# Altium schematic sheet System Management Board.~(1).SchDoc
size 594 x 420 mm
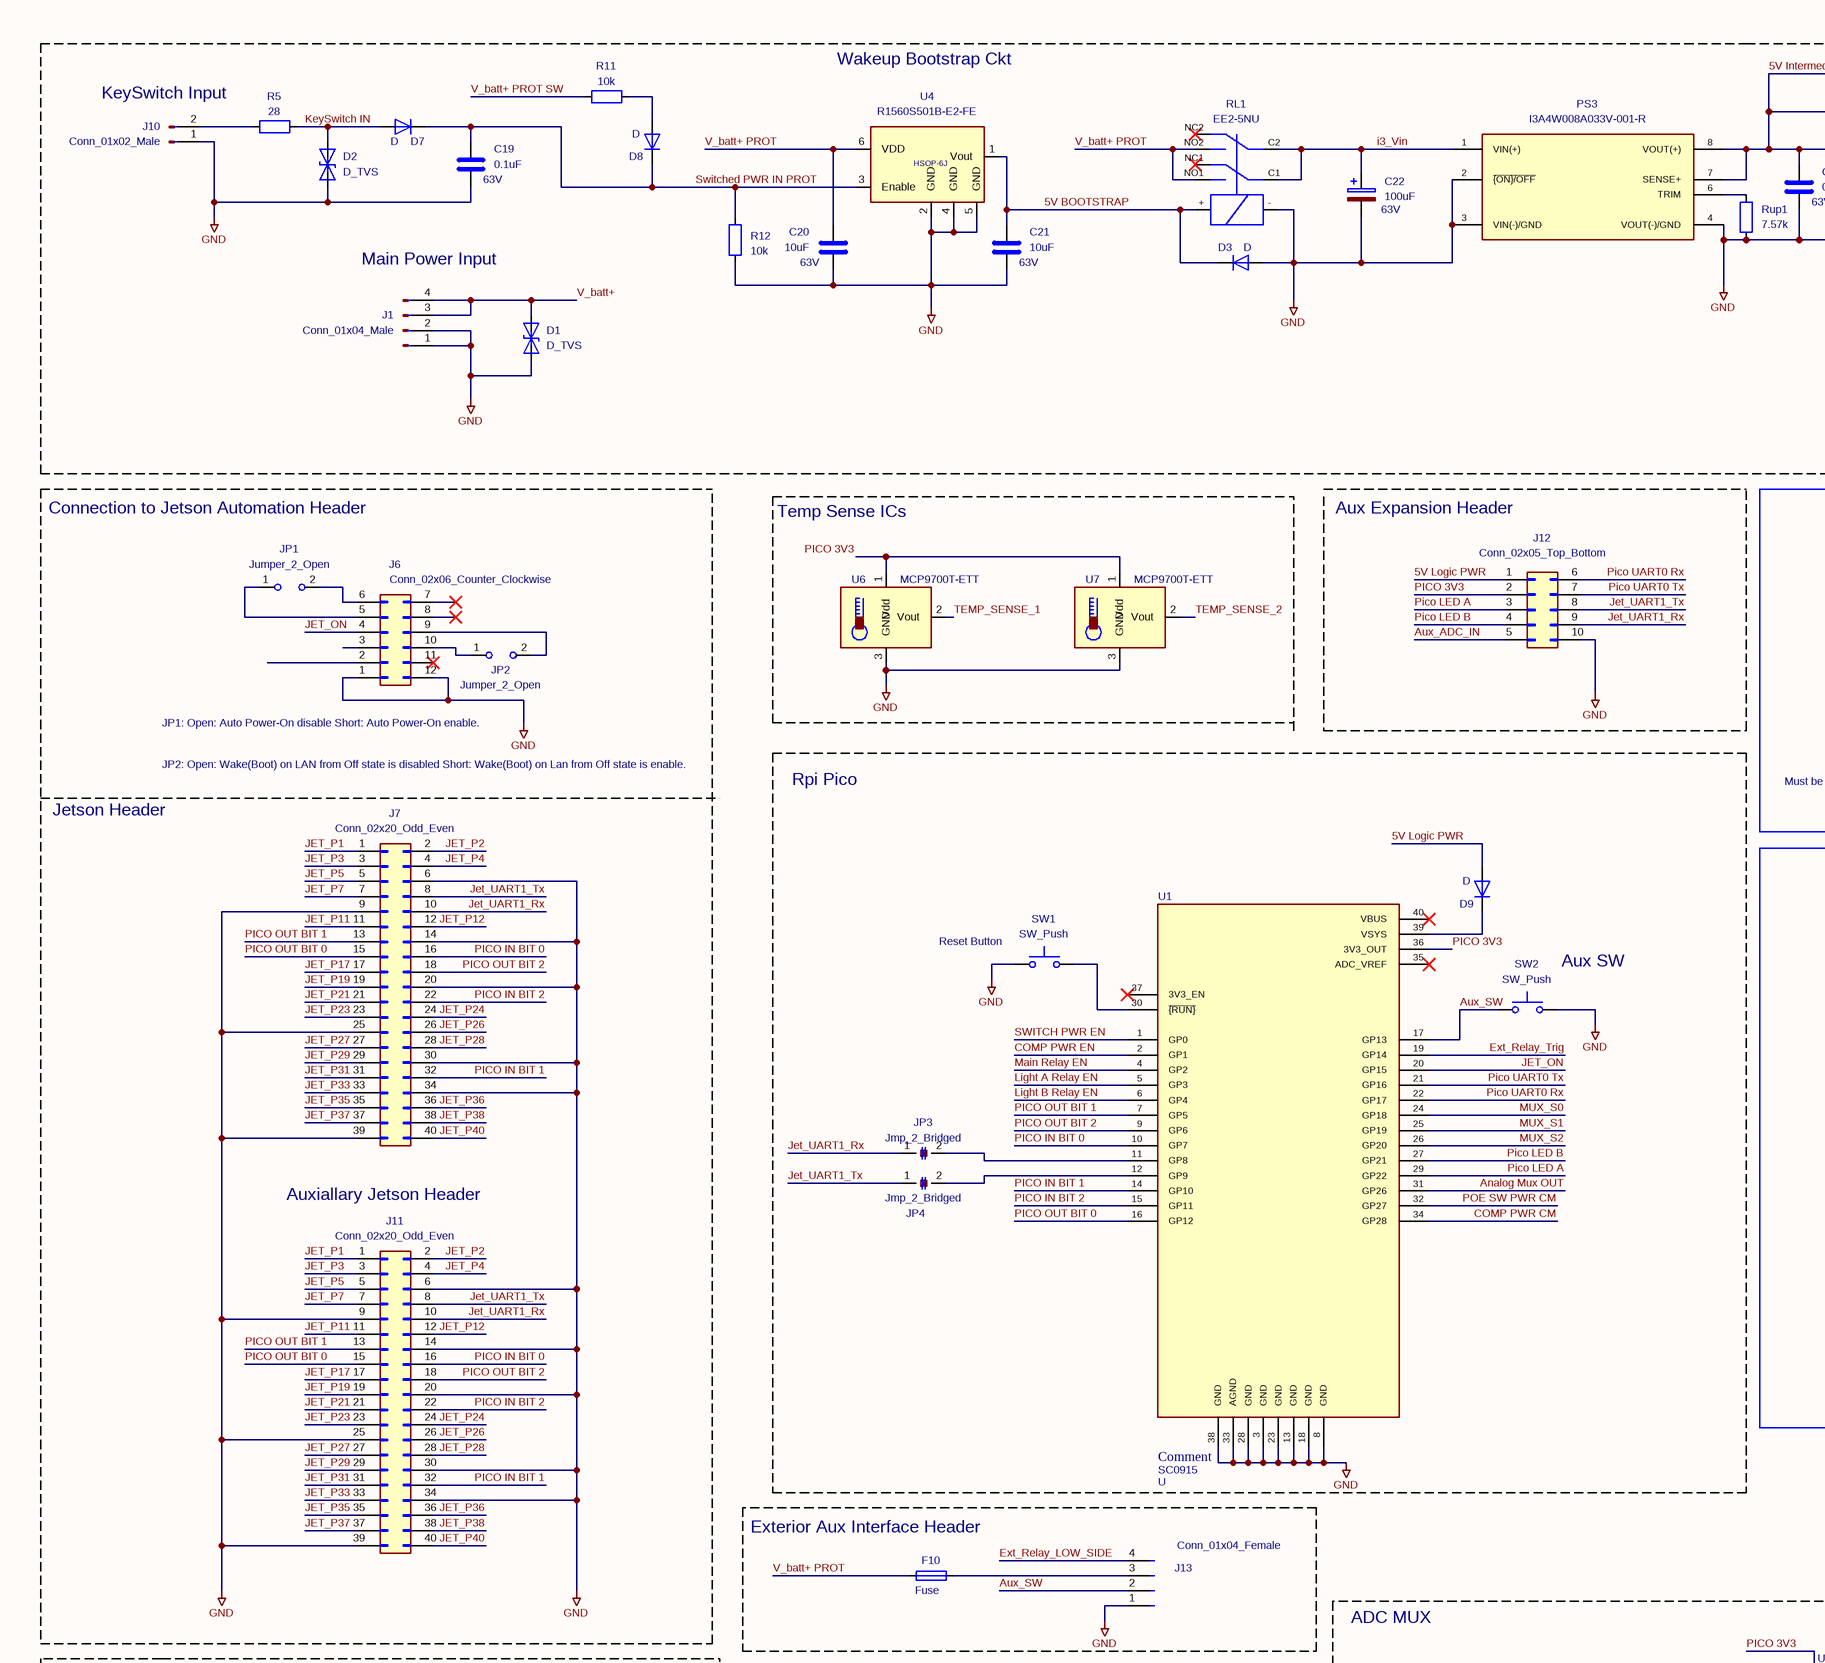
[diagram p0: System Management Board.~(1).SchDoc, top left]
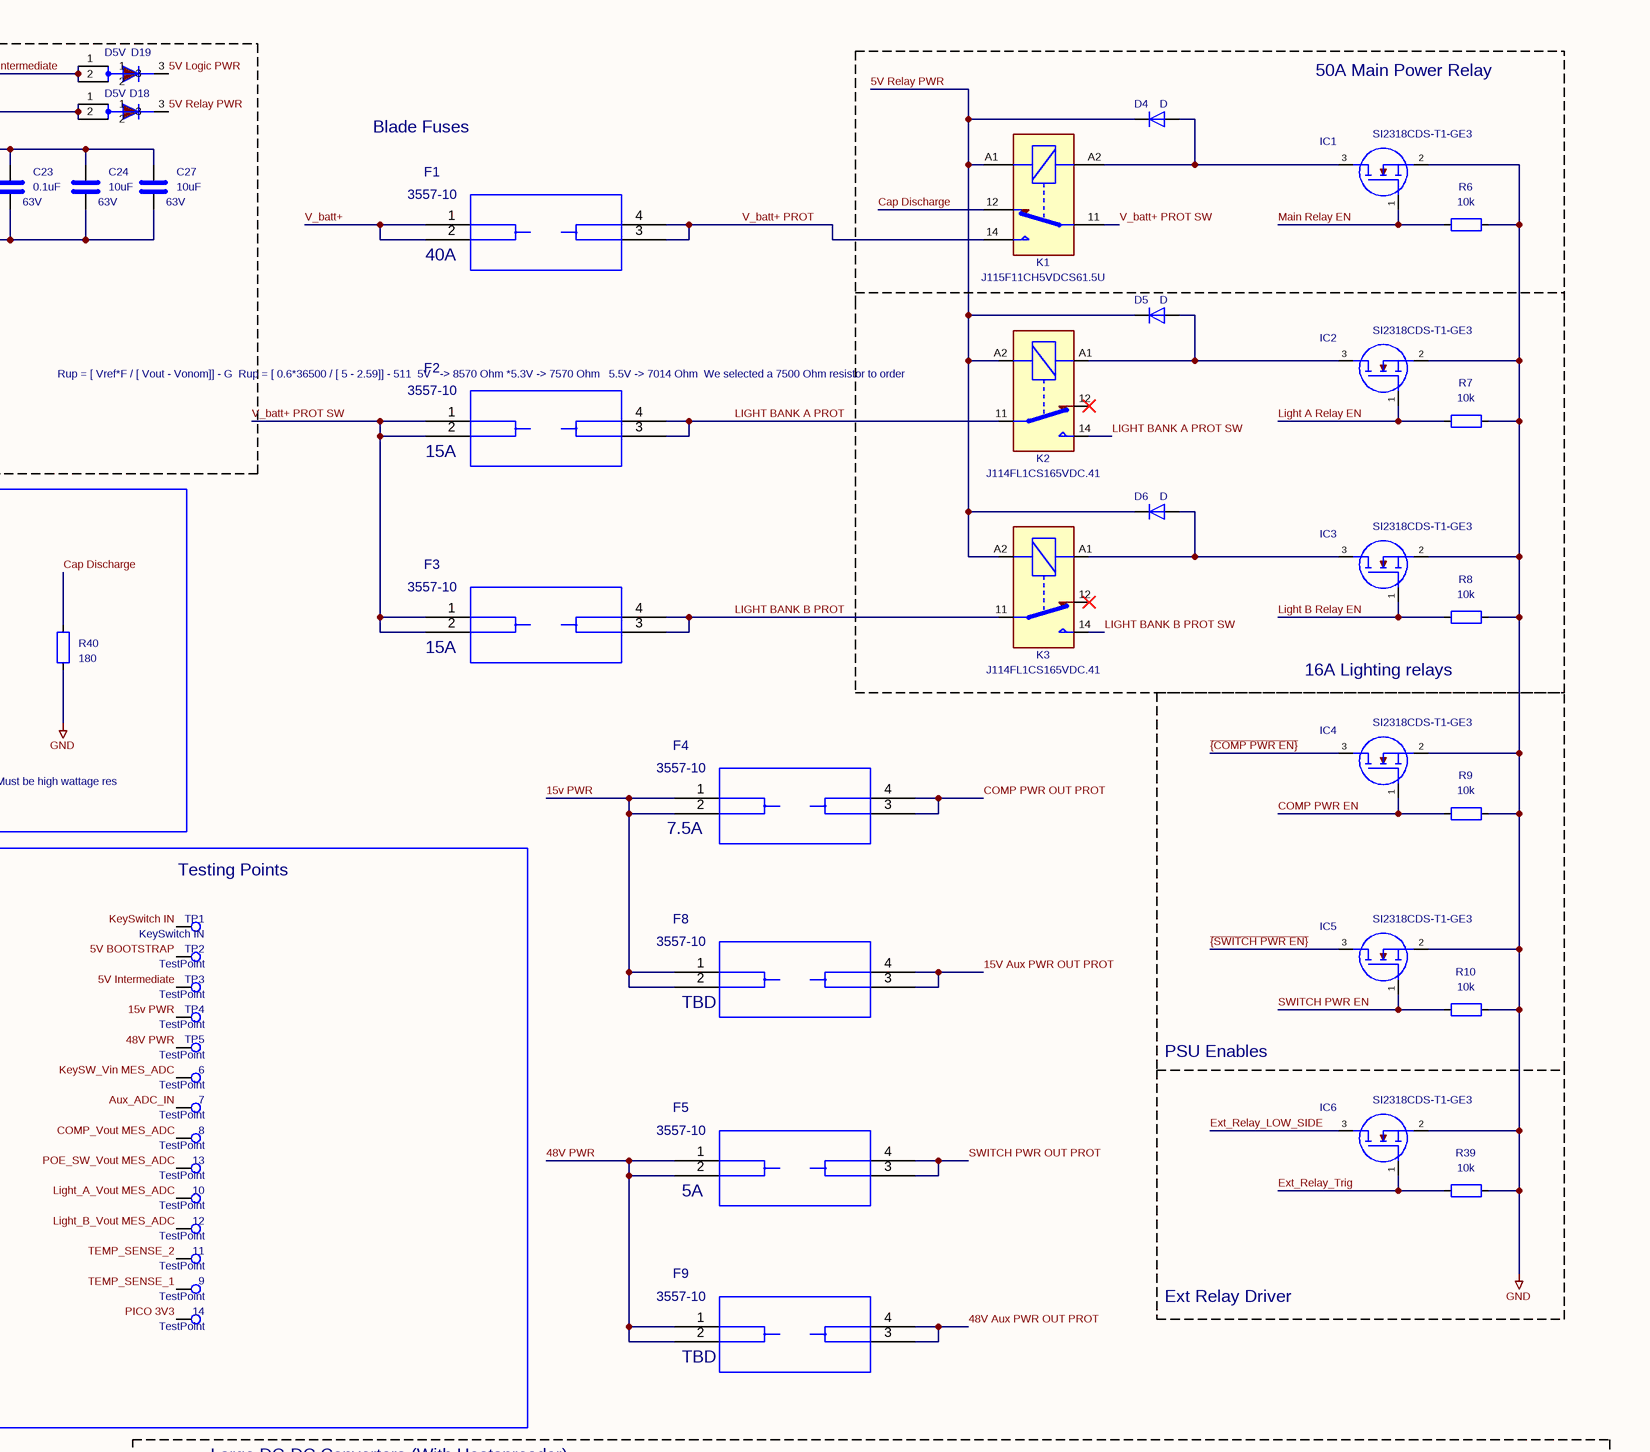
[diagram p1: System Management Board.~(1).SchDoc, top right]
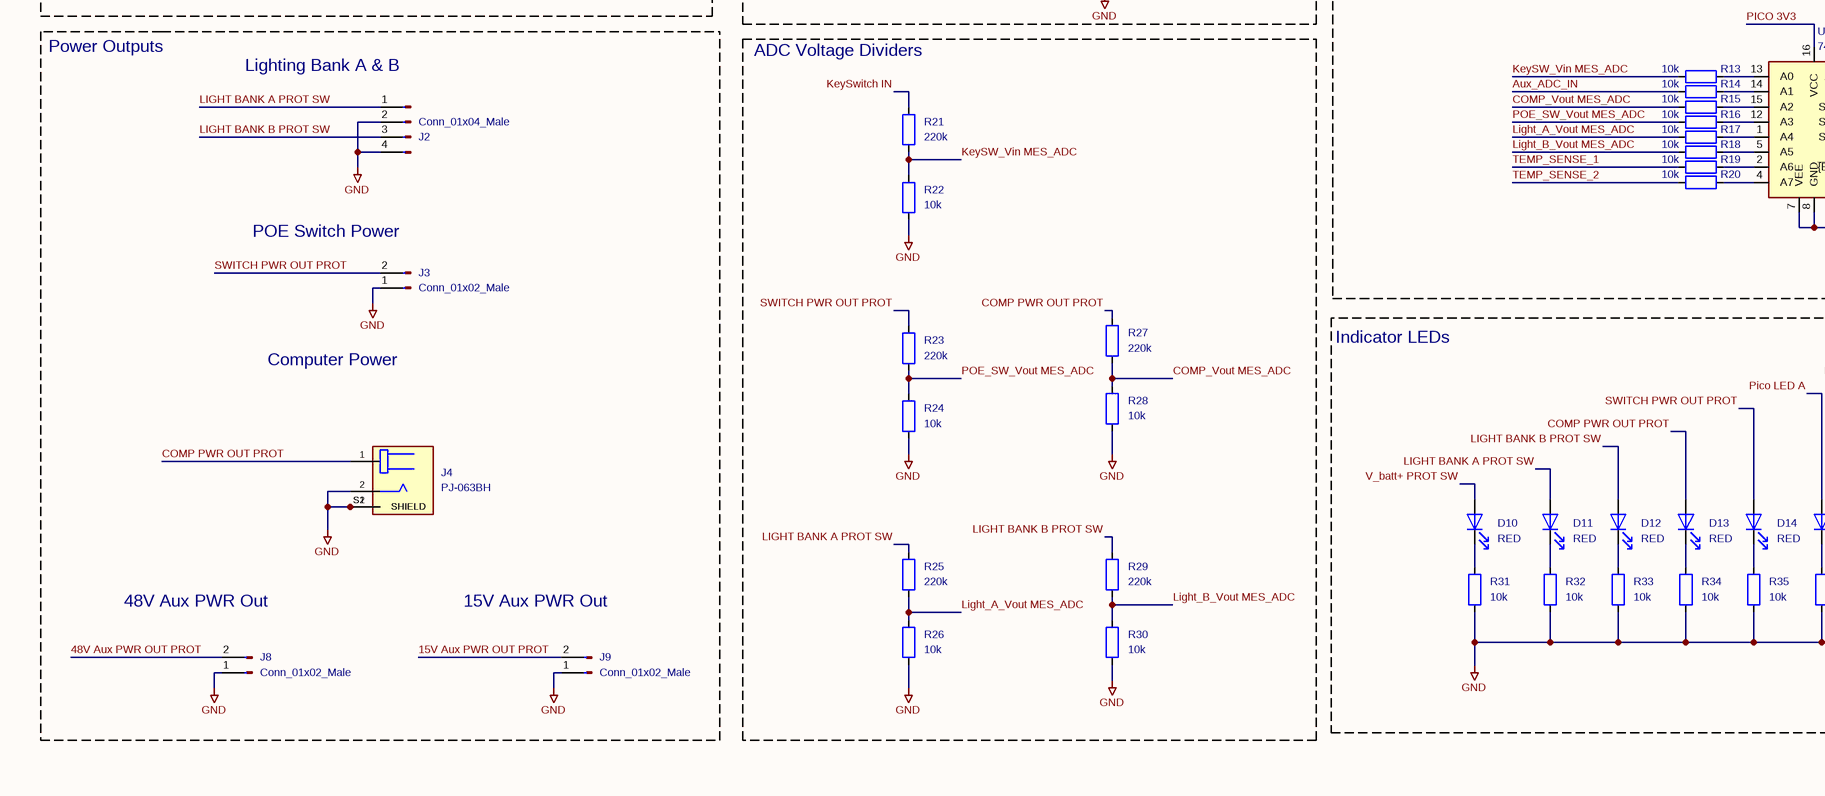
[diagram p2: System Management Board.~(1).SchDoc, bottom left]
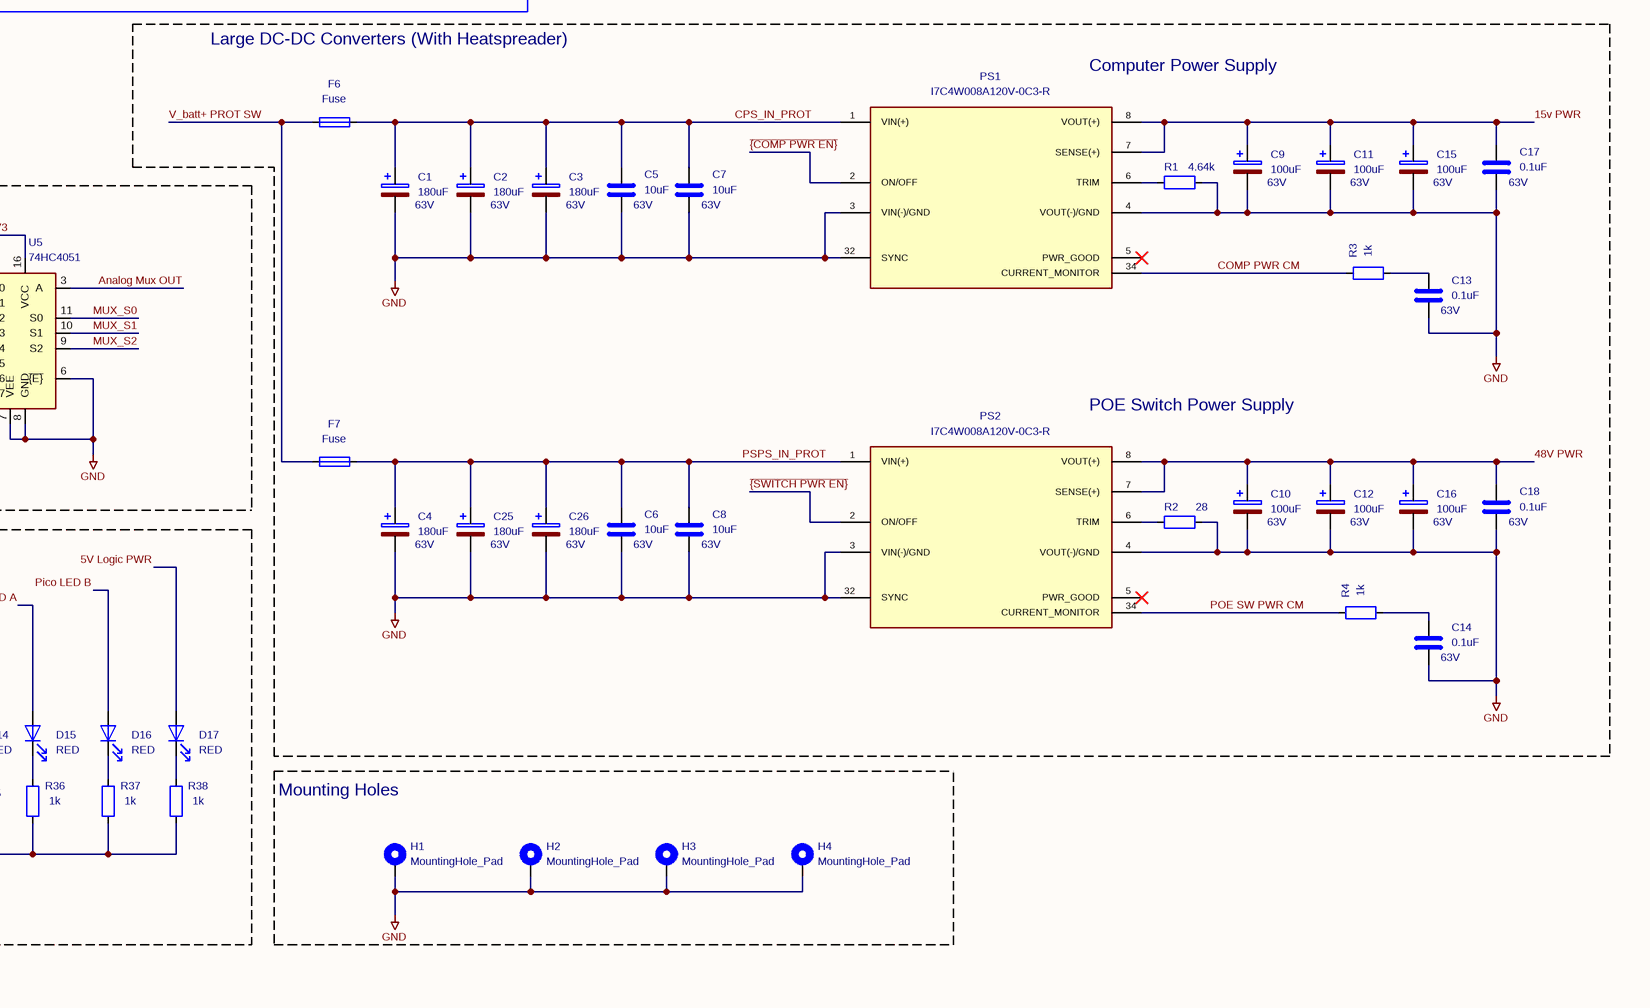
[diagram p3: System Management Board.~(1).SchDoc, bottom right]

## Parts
6  value TestPoint  [TestPoint_Pad_D1.0mm]  (hidden comment: Comment)
7  value TestPoint  [TestPoint_Pad_D1.0mm]  (hidden comment: Comment)
8  value TestPoint  [TestPoint_Pad_D1.0mm]  (hidden comment: Comment)
9  value TestPoint  [TestPoint_Pad_D1.0mm]  (hidden comment: Comment)
10  value TestPoint  [TestPoint_Pad_D1.0mm]  (hidden comment: Comment)
11  value TestPoint  [TestPoint_Pad_D1.0mm]  (hidden comment: Comment)
12  value TestPoint  [TestPoint_Pad_D1.0mm]  (hidden comment: Comment)
13  value TestPoint  [TestPoint_Pad_D1.0mm]  (hidden comment: Comment)
14  value TestPoint  [TestPoint_Pad_D1.0mm]  (hidden comment: Comment)
C1  value 180uF  Voltage: 63V  [CP_Elec_10x12.6]  (hidden comment: Comment)
C2  value 180uF  Voltage: 63V  [CP_Elec_10x12.6]  (hidden comment: Comment)
C3  value 180uF  Voltage: 63V  [CP_Elec_10x12.6]  (hidden comment: Comment)
C4  value 180uF  Voltage: 63V  [CP_Elec_10x12.6]  (hidden comment: Comment)
C5  value 10uF  Voltage: 63V  [C_1210_3225Metric]  (hidden comment: Comment)
C6  value 10uF  Voltage: 63V  [C_1210_3225Metric]  (hidden comment: Comment)
C7  value 10uF  Voltage: 63V  [C_1210_3225Metric]  (hidden comment: Comment)
C8  value 10uF  Voltage: 63V  [C_1210_3225Metric]  (hidden comment: Comment)
C9  value 100uF  Voltage: 63V  [CP_Elec_10x12.6]  (hidden comment: Comment)
C10  value 100uF  Voltage: 63V  [CP_Elec_10x12.6]  (hidden comment: Comment)
C11  value 100uF  Voltage: 63V  [CP_Elec_10x12.6]  (hidden comment: Comment)
C12  value 100uF  Voltage: 63V  [CP_Elec_10x12.6]  (hidden comment: Comment)
C13  value 0.1uF  Voltage: 63V  [C_1206_3216Metric]  (hidden comment: Comment)
C14  value 0.1uF  Voltage: 63V  [C_1206_3216Metric]  (hidden comment: Comment)
C15  value 100uF  Voltage: 63V  [CP_Elec_10x12.6]  (hidden comment: Comment)
C16  value 100uF  Voltage: 63V  [CP_Elec_10x12.6]  (hidden comment: Comment)
C17  value 0.1uF  Voltage: 63V  [C_1210_3225Metric]  (hidden comment: Comment)
C18  value 0.1uF  Voltage: 63V  [C_1210_3225Metric]  (hidden comment: Comment)
C19  value 0.1uF  Voltage: 63V  [C_1206_3216Metric]  (hidden comment: Comment)
C20  value 10uF  Voltage: 63V  [C_1210_3225Metric]  (hidden comment: Comment)
C21  value 10uF  Voltage: 63V  [C_1210_3225Metric]  (hidden comment: Comment)
C22  value 100uF  Voltage: 63V  [CP_Elec_10x12.6]  (hidden comment: Comment)
C23  value 0.1uF  Voltage: 63V  [C_1206_3216Metric]  (hidden comment: Comment)
C24  value 10uF  Voltage: 63V  [C_1210_3225Metric]  (hidden comment: Comment)
C25  value 180uF  Voltage: 63V  [CP_Elec_10x12.6]  (hidden comment: Comment)
C26  value 180uF  Voltage: 63V  [CP_Elec_10x12.6]  (hidden comment: Comment)
C27  value 10uF  Voltage: 63V  [C_1210_3225Metric]  (hidden comment: Comment)
D1  value D_TVS  [D_SMA]  (hidden comment: Comment)
D2  value D_TVS  [D_SMA]  (hidden comment: Comment)
D3  value D  [D_SOD-123F]  (hidden comment: Comment)
D4  value D  [D_SOD-123F]  (hidden comment: Comment)
D5  value D  [D_SOD-123F]  (hidden comment: Comment)
D6  value D  [D_SOD-123F]  (hidden comment: Comment)
D7  value D  [D_SOD-123F]  (hidden comment: Comment)
D8  value D  [D_SOD-123F]  (hidden comment: Comment)
D9  value D  [D_SOD-123F]  (hidden comment: Comment)
D10  value RED  [LED_1206_3216Metric]  (hidden comment: Comment)
D11  value RED  [LED_1206_3216Metric]  (hidden comment: Comment)
D12  value RED  [LED_1206_3216Metric]  (hidden comment: Comment)
D13  value RED  [LED_1206_3216Metric]  (hidden comment: Comment)
D14  value RED  [LED_1206_3216Metric]  (hidden comment: Comment)
D15  value RED  [LED_1206_3216Metric]  (hidden comment: Comment)
D16  value RED  [LED_1206_3216Metric]  (hidden comment: Comment)
D17  value RED  [LED_1206_3216Metric]  (hidden comment: Comment)
D18  value D5V  [POWERDI5_DIO]  (hidden comment: Comment)
D19  value D5V  [POWERDI5_DIO]  (hidden comment: Comment)
F1  value 3557-10  [3557-10]  (hidden comment: Comment)
F2  value 3557-10  [3557-10]  (hidden comment: Comment)
F3  value 3557-10  [3557-10]  (hidden comment: Comment)
F4  value 3557-10  [3557-10]  (hidden comment: Comment)
F5  value 3557-10  [3557-10]  (hidden comment: Comment)
F6  value Fuse  [FUSC9830X318N]  (hidden comment: Comment)
F7  value Fuse  [FUSC9830X318N]  (hidden comment: Comment)
F8  value 3557-10  [3557-10]  (hidden comment: Comment)
F9  value 3557-10  [3557-10]  (hidden comment: Comment)
F10  value Fuse  [Fuse_1206_3216Metric_Pad1.42x1.75mm_HandSolder]  (hidden comment: Comment)
H1  value MountingHole_Pad  [MountingHole_3.2mm_M3_DIN965_Pad]  (hidden comment: Comment)
H2  value MountingHole_Pad  [MountingHole_3.2mm_M3_DIN965_Pad]  (hidden comment: Comment)
H3  value MountingHole_Pad  [MountingHole_3.2mm_M3_DIN965_Pad]  (hidden comment: Comment)
H4  value MountingHole_Pad  [MountingHole_3.2mm_M3_DIN965_Pad]  (hidden comment: Comment)
IC1  value SI2318CDS-T1-GE3  [SOT95P237X112-3N]  (hidden comment: Comment)
IC2  value SI2318CDS-T1-GE3  [SOT95P237X112-3N]  (hidden comment: Comment)
IC3  value SI2318CDS-T1-GE3  [SOT95P237X112-3N]  (hidden comment: Comment)
IC4  value SI2318CDS-T1-GE3  [SOT95P237X112-3N]  (hidden comment: Comment)
IC5  value SI2318CDS-T1-GE3  [SOT95P237X112-3N]  (hidden comment: Comment)
IC6  value SI2318CDS-T1-GE3  [SOT95P237X112-3N]  (hidden comment: Comment)
J1  value Conn_01x04_Male  [1924321]  (hidden comment: Comment)
J2  value Conn_01x04_Male  [1924321]  (hidden comment: Comment)
J3  value Conn_01x02_Male  [1843606]  (hidden comment: Comment)
J4  value PJ-063BH  [CUI_PJ-063BH]  (hidden comment: Comment)
J6  value Conn_02x06_Counter_Clockwise  [PinHeader_2x06_P2.54mm_Vertical]  (hidden comment: Comment)
J7  value Conn_02x20_Odd_Even  [PinHeader_2x20_P2.54mm_Horizontal]  (hidden comment: Comment)
J8  value Conn_01x02_Male  [1843606]  (hidden comment: Comment)
J9  value Conn_01x02_Male  [1843606]  (hidden comment: Comment)
J10  value Conn_01x02_Male  [1843606]  (hidden comment: Comment)
J11  value Conn_02x20_Odd_Even  [PinHeader_2x20_P2.54mm_Vertical]  (hidden comment: Comment)
J12  value Conn_02x05_Top_Bottom  [PinSocket_2x05_P2.54mm_Vertical]  (hidden comment: Comment)
J13  value Conn_01x04_Female  [PinHeader_1x04_P2.54mm_Vertical]  (hidden comment: Comment)
JP1  value Jumper_2_Open  [PinHeader_1x02_P2.54mm_Vertical]  (hidden comment: Comment)
JP2  value Jumper_2_Open  [PinHeader_1x02_P2.54mm_Vertical]  (hidden comment: Comment)
JP3  value Jmp_2_Bridged  [SolderJumper-2_P1.3mm_Bridged_Pad1.0x1.5mm]  (hidden comment: Comment)
JP4  value Jmp_2_Bridged  [SolderJumper-2_P1.3mm_Bridged_Pad1.0x1.5mm]  (hidden comment: Comment)
K1  value J115F11CH5VDCS61.5U  [Relay_SPDT_RAYEX-L90S]  (hidden comment: Comment)
K2  value J114FL1CS165VDC.41  [Big Pads - Relay_SPDT_Schrack-RT1-16A-FormC_RM5mm]  (hidden comment: Comment)
K3  value J114FL1CS165VDC.41  [Big Pads - Relay_SPDT_Schrack-RT1-16A-FormC_RM5mm]  (hidden comment: Comment)
PS1  value I7C4W008A120V-0C3-R  [CONV_I7C4W008A120V-0C3-R]  (hidden comment: Comment)
PS2  value I7C4W008A120V-0C3-R  [CONV_I7C4W008A120V-0C3-R]  (hidden comment: Comment)
PS3  value I3A4W008A033V-001-R  [CONV_I3A4W008A033V-001-R]  (hidden comment: Comment)
R1  value 4.64k  [R_1206_3216Metric]  (hidden comment: Comment)
R2  value 28  [R_1206_3216Metric]  (hidden comment: Comment)
R3  value 1k  [R_1206_3216Metric]  (hidden comment: Comment)
R4  value 1k  [R_1206_3216Metric]  (hidden comment: Comment)
R5  value 28  [R_1206_3216Metric]  (hidden comment: Comment)
R6  value 10k  [R_1206_3216Metric]  (hidden comment: Comment)
R7  value 10k  [R_1206_3216Metric]  (hidden comment: Comment)
R8  value 10k  [R_1206_3216Metric]  (hidden comment: Comment)
R9  value 10k  [R_1206_3216Metric]  (hidden comment: Comment)
R10  value 10k  [R_1206_3216Metric]  (hidden comment: Comment)
R11  value 10k  [R_1206_3216Metric]  (hidden comment: Comment)
R12  value 10k  [R_1206_3216Metric]  (hidden comment: Comment)
R13  value 10k  [R_1206_3216Metric]  (hidden comment: Comment)
R14  value 10k  [R_1206_3216Metric]  (hidden comment: Comment)
R15  value 10k  [R_1206_3216Metric]  (hidden comment: Comment)
R16  value 10k  [R_1206_3216Metric]  (hidden comment: Comment)
R17  value 10k  [R_1206_3216Metric]  (hidden comment: Comment)
R18  value 10k  [R_1206_3216Metric]  (hidden comment: Comment)
R19  value 10k  [R_1206_3216Metric]  (hidden comment: Comment)
R20  value 10k  [R_1206_3216Metric]  (hidden comment: Comment)
R21  value 220k  [R_1206_3216Metric]  (hidden comment: Comment)
R22  value 10k  [R_1206_3216Metric]  (hidden comment: Comment)
R23  value 220k  [R_1206_3216Metric]  (hidden comment: Comment)
R24  value 10k  [R_1206_3216Metric]  (hidden comment: Comment)
R25  value 220k  [R_1206_3216Metric]  (hidden comment: Comment)
R26  value 10k  [R_1206_3216Metric]  (hidden comment: Comment)
R27  value 220k  [R_1206_3216Metric]  (hidden comment: Comment)
R28  value 10k  [R_1206_3216Metric]  (hidden comment: Comment)
R29  value 220k  [R_1206_3216Metric]  (hidden comment: Comment)
R30  value 10k  [R_1206_3216Metric]  (hidden comment: Comment)
R31  value 10k  [R_1206_3216Metric]  (hidden comment: Comment)
R32  value 10k  [R_1206_3216Metric]  (hidden comment: Comment)
R33  value 10k  [R_1206_3216Metric]  (hidden comment: Comment)
R34  value 10k  [R_1206_3216Metric]  (hidden comment: Comment)
R35  value 10k  [R_1206_3216Metric]  (hidden comment: Comment)
R36  value 1k  [R_1206_3216Metric]  (hidden comment: Comment)
R37  value 1k  [R_1206_3216Metric]  (hidden comment: Comment)
R38  value 1k  [R_1206_3216Metric]  (hidden comment: Comment)
R39  value 10k  [R_1206_3216Metric]  (hidden comment: Comment)
R40  value 180  [RES_3540_TEC]  (hidden comment: Comment)
RL1  value EE2-5NU  [EE2-5NU]  (hidden comment: Comment)
Rup1  value 7.57k  [R_1206_3216Metric]  (hidden comment: Comment)
SW1  value SW_Push  [SW_TL3305BF260QG]  (hidden comment: Comment)
SW2  value SW_Push  [SW_TL3305BF260QG]  (hidden comment: Comment)
TP1  value KeySwitch IN  [TestPoint_Pad_D1.0mm]  (hidden comment: Comment)
TP2  value TestPoint  [TestPoint_Pad_D1.0mm]  (hidden comment: Comment)
TP3  value TestPoint  [TestPoint_Pad_D1.0mm]  (hidden comment: Comment)
TP4  value TestPoint  [TestPoint_Pad_D1.0mm]  (hidden comment: Comment)
TP5  value TestPoint  [TestPoint_Pad_D1.0mm]  (hidden comment: Comment)
U1  Comment  value SC0915  Reference: U  [MODULE_SCO915_Custom_HeaderStyle]
U4  value R1560S501B-E2-FE  [HSOP-6J]  (hidden comment: Comment)
U5  value 74HC4051  [TSSOP-16_4.4x5mm_P0.65mm]  (hidden comment: Comment)
U6  value MCP9700T-ETT  [SOT-23]  (hidden comment: Comment)
U7  value MCP9700T-ETT  [SOT-23]  (hidden comment: Comment)

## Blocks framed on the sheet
Must be high wattage res: R40
Testing Points: 6-14 TP1-TP5
Exterior Aux Interface Header: F10 J13
ADC Voltage Dividers: R21-R30
Indicator LEDs: D10-D17 R31-R38
Mounting Holes: H1-H4

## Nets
GND: C1.2 C2.2 C3.2 C4.2 C5.2 C6.2 C7.2 C8.2 C9.2 C10.2 C11.2 C12.2 C13.2 C14.2 C15.2 C16.2 C17.2 C18.2 C19.2 C20.2 C21.2 C22.2 C23.2 C24.2 C25.2 C26.2 C27.2 D1.1(A1) D2.1(A1) D3.2(A) H1.1 H2.1 H3.1 H4.1 IC1.2 IC2.2 IC3.2 IC4.2 IC5.2 IC6.2 J1.1(Pin_1) J1.2(Pin_2) J2.2(Pin_2) J2.4(Pin_4) J3.1(Pin_1) J4.2 J4.S1(SHIELD) J4.S2(SHIELD) J6.1(Pin_1) J6.12(Pin_12) J7.6(Pin_6) J7.9(Pin_9) J7.14(Pin_14) J7.20(Pin_20) J7.25(Pin_25) J7.30(Pin_30) J7.34(Pin_34) J7.39(Pin_39) J8.1(Pin_1) J9.1(Pin_1) J10.1(Pin_1) J11.6(Pin_6) J11.9(Pin_9) J11.14(Pin_14) J11.20(Pin_20) J11.25(Pin_25) J11.30(Pin_30) J11.34(Pin_34) J11.39(Pin_39) J12.10(Pin_10) J13.1(Pin_1) PS1.3(VIN(-)/GND) PS1.4(VOUT(-)/GND) PS1.32(SYNC) PS2.3(VIN(-)/GND) PS2.4(VOUT(-)/GND) PS2.32(SYNC) PS3.2(~{{ON}/OFF}) PS3.3(VIN(-)/GND) PS3.4(VOUT(-)/GND) R1.2 R2.2 R6.2 R7.2 R8.2 R9.2 R10.2 R12.1 R22.2 R24.2 R26.2 R28.2 R30.2 R31.2 R32.2 R33.2 R34.2 R35.2 R36.1 R37.1 R38.1 R39.2 R40.2 RL1.- Rup1.1 SW1.1 SW2.2 U1.3(GND) U1.8(GND) U1.13(GND) U1.18(GND) U1.23(GND) U1.28(GND) U1.33(AGND) U1.38(GND) U4.2(GND) U4.4(GND) U4.5(GND) U5.6(~{{E}}) U5.7(VEE) U5.8(GND) U6.3(GND) U7.3(GND)
5V BOOTSTRAP: C21.1 D3.1(K) RL1.+ TP2.1 U4.1(Vout)
5V Intermediate: C23.1 C24.1 C27.1 D18.1 D18.2 D19.1 D19.2 PS3.7(SENSE+) PS3.8(VOUT(+)) TP3.1
5V Logic PWR: D9.2(A) D17.2(A) D19.3 J12.1(Pin_1)
5V Relay PWR: D4.1(K) D5.1(K) D6.1(K) D18.3 K1.A1 K2.A2 K3.A2
15V Aux PWR OUT PROT: F8.3 F8.4 J9.2(Pin_2)
15v PWR: C9.1 C11.1 C15.1 C17.1 F4.1 F4.2 F8.1 F8.2 PS1.7(SENSE(+)) PS1.8(VOUT(+)) TP4.1
48V Aux PWR OUT PROT: F9.3 F9.4 J8.2(Pin_2)
48V PWR: C10.1 C12.1 C16.1 C18.1 F5.1 F5.2 F9.1 F9.2 PS2.7(SENSE(+)) PS2.8(VOUT(+)) TP5.1
Analog Mux OUT: U1.31(GP26) U5.3(A)
Aux_ADC_IN: 7.1 J12.5(Pin_5) R14.1
Aux_SW: J13.2(Pin_2) SW2.1 U1.17(GP13)
Cap Discharge: K1.12 R40.1
COMP PWR CM: PS1.34(CURRENT_MONITOR) R3.2 U1.34(GP28)
COMP PWR EN: IC4.1 R9.1 U1.2(GP1)
COMP PWR OUT PROT: D13.2(A) F4.3 F4.4 J4.1 R27.2
COMP_Vout MES_ADC: 8.1 R15.1 R27.1 R28.1
CPS_IN_PROT: C1.1 C2.1 C3.1 C5.1 C7.1 F6.2 PS1.1(VIN(+))
Ext_Relay_LOW_SIDE: IC6.3 J13.4(Pin_4)
Ext_Relay_Trig: IC6.1 R39.1 U1.19(GP14)
i3_Vin: C22.1 PS3.1(VIN(+)) RL1.C1 RL1.C2
JET_ON: J6.4(Pin_4) U1.20(GP15)
JET_P1: J7.1(Pin_1) J11.1(Pin_1)
JET_P2: J7.2(Pin_2) J11.2(Pin_2)
JET_P3: J7.3(Pin_3) J11.3(Pin_3)
JET_P4: J7.4(Pin_4) J11.4(Pin_4)
JET_P5: J7.5(Pin_5) J11.5(Pin_5)
JET_P7: J7.7(Pin_7) J11.7(Pin_7)
JET_P11: J7.11(Pin_11) J11.11(Pin_11)
JET_P12: J7.12(Pin_12) J11.12(Pin_12)
JET_P17: J7.17(Pin_17) J11.17(Pin_17)
JET_P19: J7.19(Pin_19) J11.19(Pin_19)
JET_P21: J7.21(Pin_21) J11.21(Pin_21)
JET_P23: J7.23(Pin_23) J11.23(Pin_23)
JET_P24: J7.24(Pin_24) J11.24(Pin_24)
JET_P26: J7.26(Pin_26) J11.26(Pin_26)
JET_P27: J7.27(Pin_27) J11.27(Pin_27)
JET_P28: J7.28(Pin_28) J11.28(Pin_28)
JET_P29: J7.29(Pin_29) J11.29(Pin_29)
JET_P31: J7.31(Pin_31) J11.31(Pin_31)
JET_P33: J7.33(Pin_33) J11.33(Pin_33)
JET_P35: J7.35(Pin_35) J11.35(Pin_35)
JET_P36: J7.36(Pin_36) J11.36(Pin_36)
JET_P37: J7.37(Pin_37) J11.37(Pin_37)
JET_P38: J7.38(Pin_38) J11.38(Pin_38)
JET_P40: J7.40(Pin_40) J11.40(Pin_40)
Jet_UART1_Rx: J7.10(Pin_10) J11.10(Pin_10) J12.9(Pin_9) JP3.1(A)
Jet_UART1_Tx: J7.8(Pin_8) J11.8(Pin_8) J12.8(Pin_8) JP4.1(A)
KeySW_Vin MES_ADC: 6.1 R13.1 R21.1 R22.1
KeySwitch IN: D2.2(A2) D7.2(A) R5.2 R21.2 TP1.1
Light A Relay EN: IC2.1 R7.1 U1.5(GP3)
Light B Relay EN: IC3.1 R8.1 U1.6(GP4)
LIGHT BANK A PROT: F2.3 F2.4 K2.11
LIGHT BANK A PROT SW: D11.2(A) J2.1(Pin_1) K2.14 R25.2
LIGHT BANK B PROT: F3.3 F3.4 K3.11
LIGHT BANK B PROT SW: D12.2(A) J2.3(Pin_3) K3.14 R29.2
Light_A_Vout MES_ADC: 10.1 R17.1 R25.1 R26.1
Light_B_Vout MES_ADC: 12.1 R18.1 R29.1 R30.1
Main Relay EN: IC1.1 R6.1 U1.4(GP2)
MUX_S0: U1.24(GP18) U5.11(S0)
MUX_S1: U1.25(GP19) U5.10(S1)
MUX_S2: U1.26(GP20) U5.9(S2)
PICO 3V3: 14.1 J12.2(Pin_2) U1.36(3V3_OUT) U5.16(VCC) U6.1(Vdd) U7.1(Vdd)
PICO IN BIT 0: J7.16(Pin_16) J11.16(Pin_16) U1.10(GP7)
PICO IN BIT 1: J7.32(Pin_32) J11.32(Pin_32) U1.14(GP10)
PICO IN BIT 2: J7.22(Pin_22) J11.22(Pin_22) U1.15(GP11)
Pico LED A: D15.2(A) J12.3(Pin_3) U1.29(GP22)
Pico LED B: D16.2(A) J12.4(Pin_4) U1.27(GP21)
PICO OUT BIT 0: J7.15(Pin_15) J11.15(Pin_15) U1.16(GP12)
PICO OUT BIT 1: J7.13(Pin_13) J11.13(Pin_13) U1.7(GP5)
PICO OUT BIT 2: J7.18(Pin_18) J11.18(Pin_18) U1.9(GP6)
Pico UART0 Rx: J12.6(Pin_6) U1.22(GP17)
Pico UART0 Tx: J12.7(Pin_7) U1.21(GP16)
POE SW PWR CM: PS2.34(CURRENT_MONITOR) R4.2 U1.32(GP27)
POE_SW_Vout MES_ADC: 13.1 R16.1 R23.1 R24.1
PSPS_IN_PROT: C4.1 C6.1 C8.1 C25.1 C26.1 F7.2 PS2.1(VIN(+))
SWITCH PWR EN: IC5.1 R10.1 U1.1(GP0)
SWITCH PWR OUT PROT: D14.2(A) F5.3 F5.4 J3.2(Pin_2) R23.2
Switched PWR IN PROT: C19.1 D7.1(K) D8.1(K) R12.2 U4.3(Enable)
TEMP_SENSE_1: 9.1 R19.1 U6.2(Vout)
TEMP_SENSE_2: 11.1 R20.1 U7.2(Vout)
V_batt+: D1.2(A2) F1.1 F1.2 J1.3(Pin_3) J1.4(Pin_4)
V_batt+ PROT: C20.1 F1.3 F1.4 F10.1 K1.14 RL1.NO1 RL1.NO2 U4.6(VDD)
V_batt+ PROT SW: D10.2(A) F2.1 F2.2 F3.1 F3.2 F6.1 F7.1 K1.11 R11.1
~{{COMP PWR EN}}: IC4.3 PS1.2(ON/OFF)
~{{SWITCH PWR EN}}: IC5.3 PS2.2(ON/OFF)
NetC13_1: C13.1 R3.1
NetC14_1: C14.1 R4.1
NetD4_2: D4.2(A) IC1.3 K1.A2
NetD5_2: D5.2(A) IC2.3 K2.A1
NetD6_2: D6.2(A) IC3.3 K3.A1
NetD8_2: D8.2(A) R11.2
NetD9_1: D9.1(K) U1.39(VSYS)
NetD10_1: D10.1(K) R31.1
NetD11_1: D11.1(K) R32.1
NetD12_1: D12.1(K) R33.1
NetD13_1: D13.1(K) R34.1
NetD14_1: D14.1(K) R35.1
NetD15_1: D15.1(K) R36.2
NetD16_1: D16.1(K) R37.2
NetD17_1: D17.1(K) R38.2
NetF10_2: F10.2 J13.3(Pin_3)
NetJ6_5: J6.5(Pin_5) JP1.1(A)
NetJ6_6: J6.6(Pin_6) JP1.2(B)
NetJ6_9: J6.9(Pin_9) JP2.2(B)
NetJ6_10: J6.10(Pin_10) JP2.1(A)
NetJ10_2: J10.2(Pin_2) R5.1
NetJP3_2: JP3.2(B) U1.11(GP8)
NetJP4_2: JP4.2(B) U1.12(GP9)
NetPS1_6: PS1.6(TRIM) R1.1
NetPS2_6: PS2.6(TRIM) R2.1
NetPS3_6: PS3.6(TRIM) Rup1.2
NetR13_2: R13.2 U5.13(A0)
NetR14_2: R14.2 U5.14(A1)
NetR15_2: R15.2 U5.15(A2)
NetR16_2: R16.2 U5.12(A3)
NetR17_2: R17.2 U5.1(A4)
NetR18_2: R18.2 U5.5(A5)
NetR19_2: R19.2 U5.2(A6)
NetR20_2: R20.2 U5.4(A7)
NetSW1_2: SW1.2 U1.30(~{{RUN}})

Not connected (* = marked no-connect by the designer): J6 2(Pin_2) 3(Pin_3) 7(Pin_7)* 8(Pin_8)* 11(Pin_11)*; K2 12*; K3 12*; PS1 5(PWR_GOOD)*; PS2 5(PWR_GOOD)*; RL1 NC1* NC2*; U1 35(ADC_VREF)* 37(3V3_EN)* 40(VBUS)*

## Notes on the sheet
- KeySwitch Input
- Wakeup Bootstrap Ckt
- Blade Fuses
- 50A Main Power Relay
- (near J1) Main Power Input
- (near F1) 40A
- (near K2) Rup = [ Vref*F / [ Vout - Vonom]] - G
  Rup = [ 0.6*36500 / [ 5 - 2.59]] - 511
  5V   -> 8570 Ohm
  *5.3V -> 7570 Ohm
  5.5V -> 7014 Ohm
  We selected a 7500 Ohm resistor to order
- Connection to Jetson Automation Header
- Aux Expansion Header
- (near F2) 15A
- Temp Sense ICs
- (near F3) 15A
- JP1:
  Open: Auto Power-On disable
  Short: Auto Power-On enable.
- (near R8) 16A Lighting relays
- Jetson Header
- JP2:
  Open: Wake(Boot) on LAN from Off state is disabled
  Short: Wake(Boot) on Lan from Off state is enable.
- Rpi Pico
- (near F4) 7.5A
- (near SW1) Reset Button
- (near SW2) Aux SW
- (near F8) TBD
- PSU Enables
- Auxiallary Jetson Header
- (near F5) 5A
- Ext Relay Driver
- (near F9) TBD
- Large DC-DC Converters (With Heatspreader)
- (near PS1) Computer Power Supply
- ADC MUX
- Power Outputs
- (near J2) Lighting Bank A & B
- (near J3) POE Switch Power
- (near PS2) POE Switch Power Supply
- Computer Power
- (near J8) 48V Aux PWR Out
- (near J9) 15V Aux PWR Out

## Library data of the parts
6-14 TP1-TP5 = TestPoint
C1-C4 C9-C12 C15 C16 C22 C25 C26 = C_Polarized
C5-C8 C13 C14 C17-C21 C23 C24 C27 = C
D1 D2 = D_TVS
D3-D9 = D
D10-D17 = LED
D18 = SBRT15U50SP5-13_1
D19 = SBRT15U50SP5-13
F1-F5 F8 F9 = 3557-10
F6 F7 F10 = Fuse
H1-H4 = MountingHole_Pad
IC1-IC6 = SI2318CDS-T1-GE3: MANUFACTURER_NAME: Vishay
J1 J2 = Conn_01x04_Male
J3 J8-J10 = Conn_01x02_Male
J4 = PJ-063BH: MANUFACTURER: CUI INC
J6 = Conn_02x06_Counter_Clockwise
J7 J11 = Conn_02x20_Odd_Even
J12 = Conn_02x05_Top_Bottom
J13 = Conn_01x04_Female
JP1 JP2 = Jumper_2_Open
JP3 JP4 = SolderJumper_2_Bridged
K1 = RAYEX-L90S
K2 K3 = J114FL1CS165VDC.41
PS1 PS2 = I7C4W008A120V-0C3-R: MANUFACTURER: TDK; SNAPEDA_PN: i7C4W012A050V-0C3-R
PS3 = I3A4W008A033V-001-R: MANUFACTURER: TDK-Lambda
R1-R40 Rup1 = R
RL1 = EE2-5NU
SW1 = SW_Push_4_PIN_1
SW2 = SW_Push_4_PIN
U1 = SC0915: MANUFACTURER: Raspberry Pi
U4 = R1560S501B-E2-FE: test
U5 = 74HC4051
U6 U7 = MCP9700T-ETT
